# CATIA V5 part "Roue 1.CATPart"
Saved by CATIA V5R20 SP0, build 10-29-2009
Part number: roue 1
Bounding box of the stored display mesh (mm): x -50 to 50, y -50 to 50, z 0 to 20
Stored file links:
  E:\EDELI\wjacquemont\Edeli_2012_122_wjacquemont\Roue 1.CATPart
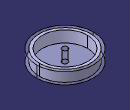
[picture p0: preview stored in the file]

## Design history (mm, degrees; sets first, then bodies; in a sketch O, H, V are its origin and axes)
Body1 (main body)
  Sketch1 on xy-plane, origin (0, 0, 0), H (1, 0, 0), V (0, 1, 0)
    circle A1 centre (0, 0) radius 5
    circle A2 centre (0, 0) radius 40
    radius A1 = 5
    radius A2 = 40
  Pad1: profile Sketch1, direction (0, 0, 1), length 20
Body2
  Sketch2 on end face of Pad1, origin (0, 0, 20), H (1, 0, 0), V (0, 1, 0)
    circle A1 centre (0, 0) radius 45
    circle A2 centre (0, 0) radius 40
    reference projected circle E1 centre (0, 0) radius 40 from edge [face of Pad1 from Sketch1.A2 | end face of Pad1]
    radius A1 = 45
    coincidence: E1 A2
  Pad2: profile Sketch2, direction (0, 0, -1), length 20
Body3
  Sketch3 on end face of Pad1, origin (0, 0, 20), H (1, 0, 0), V (0, 1, 0)
    circle A1 centre (0, 0) radius 50
    circle A2 centre (0, 0) radius 45
    reference projected circle E1 centre (0, 0) radius 45 from edge [face of Pad2 from Sketch2.A1 | start face of Pad2]
    radius A1 = 50
    coincidence: E1 A2
  Pad3: profile Sketch3, direction (0, 0, -1), length 20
